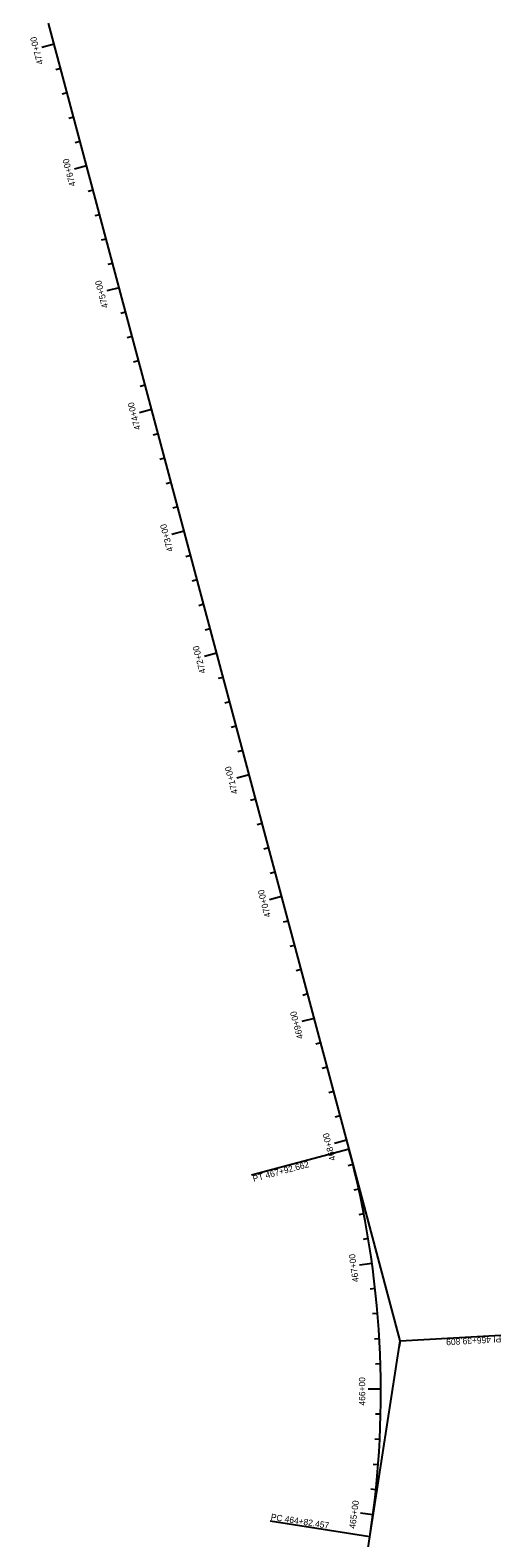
# Model space of a CAD drawing. Extents: x 187748 to 191086, y 249974 to 259749.
# Drawn here: x 189339 to 189712, y 253177 to 254373 of the extents above; entities that cross this region are included whole.
import ezdxf

# ---------------------------------------------------------------- set-up
doc = ezdxf.new("R2010")
doc.units = 0
doc.layers.add('BORDER', color=7, linetype='Continuous')

msp = doc.modelspace()

# ---------------------------------------------------------------- linework, layer by layer
at = {"layer": 'BORDER'}
for p, q in [((189591.5, 253485.3), (189353.2, 254378.6)), ((189357.6, 254362), (189347.9, 254359.4)), ((189362.8, 254342.7), (189358.9, 254341.7)), ((189367.9, 254323.4), (189364, 254322.3)), ((189373.1, 254304), (189369.2, 254303)), ((189378.2, 254284.7), (189374.4, 254283.7)), ((189383.4, 254265.4), (189373.7, 254262.8)), ((189388.5, 254246.1), (189384.7, 254245)), ((189393.7, 254226.7), (189389.8, 254225.7)), ((189398.8, 254207.4), (189395, 254206.4)), ((189404, 254188.1), (189400.1, 254187.1)), ((189409.1, 254168.8), (189399.5, 254166.2)), ((189414.3, 254149.5), (189410.4, 254148.4)), ((189419.5, 254130.1), (189415.6, 254129.1)), ((189424.6, 254110.8), (189420.7, 254109.8)), ((189429.8, 254091.5), (189425.9, 254090.4)), ((189434.9, 254072.2), (189425.3, 254069.6)), ((189440.1, 254052.8), (189436.2, 254051.8)), ((189445.2, 254033.5), (189441.4, 254032.5)), ((189450.4, 254014.2), (189446.5, 254013.2)), ((189455.5, 253994.9), (189451.7, 253993.8)), ((189460.7, 253975.5), (189451, 253973)), ((189465.9, 253956.2), (189462, 253955.2)), ((189471, 253936.9), (189467.1, 253935.9)), ((189476.2, 253917.6), (189472.3, 253916.5)), ((189481.3, 253898.2), (189477.5, 253897.2)), ((189486.5, 253878.9), (189476.8, 253876.3)), ((189491.6, 253859.6), (189487.8, 253858.6)), ((189496.8, 253840.3), (189492.9, 253839.2)), ((189501.9, 253820.9), (189498.1, 253819.9)), ((189507.1, 253801.6), (189503.2, 253800.6)), ((189512.3, 253782.3), (189502.6, 253779.7)), ((189517.4, 253763), (189513.5, 253761.9)), ((189522.6, 253743.6), (189518.7, 253742.6)), ((189527.7, 253724.3), (189523.9, 253723.3)), ((189532.9, 253705), (189529, 253704)), ((189538, 253685.7), (189528.4, 253683.1)), ((189543.2, 253666.3), (189539.3, 253665.3)), ((189548.3, 253647), (189544.5, 253646)), ((189553.5, 253627.7), (189549.6, 253626.7)), ((189558.6, 253608.4), (189554.8, 253607.3)), ((189563.8, 253589), (189554.1, 253586.5)), ((189569, 253569.7), (189565.1, 253568.7)), ((189574.1, 253550.4), (189570.3, 253549.4)), ((189579.3, 253531.1), (189575.4, 253530)), ((189584.4, 253511.8), (189580.6, 253510.7)), ((189589.6, 253492.4), (189579.9, 253489.9)), ((189591.5, 253485.3), (189514.2, 253464.7)), ((189594.6, 253473.1), (189590.8, 253472.1)), ((189599.2, 253453.6), (189595.3, 253452.7)), ((189603.2, 253434), (189599.3, 253433.3)), ((189606.8, 253414.3), (189602.8, 253413.7)), ((189609.8, 253394.6), (189599.9, 253393.2)), ((189612.2, 253374.7), (189608.3, 253374.3)), ((189614.2, 253354.8), (189610.2, 253354.5)), ((189615.6, 253334.9), (189611.6, 253334.6)), ((189632, 253333.3), (189630.7, 253338.1)), ((189632, 253333.3), (189711.9, 253337.6)), ((189632, 253333.3), (189631.3, 253328.4)), ((189616.5, 253314.9), (189612.5, 253314.8)), ((189616.8, 253294.9), (189606.8, 253294.8)), ((189616.6, 253274.9), (189612.6, 253275)), ((189615.9, 253254.9), (189611.9, 253255.1)), ((189614.6, 253234.9), (189610.7, 253235.2)), ((189612.9, 253215), (189608.9, 253215.4)), ((189608.1, 253177.8), (189529, 253190)), ((189610.5, 253195.2), (189600.6, 253196.4)), ((189531.2, 252679.3), (189608.1, 253177.8))]:
    msp.add_line(p, q, dxfattribs=at)
msp.add_lwpolyline([(189608.1, 253177.8), (189632, 253333.3), (189591.5, 253485.3)], dxfattribs=at)
msp.add_arc((188866.8, 253292), 750, 351.2393, 14.9372, dxfattribs=at)

# ---------------------------------------------------------------- texts
for s, rotation, p in [('477+00', 104.9372, (189349.1, 254346.6)), ('476+00', 104.9372, (189374.8, 254249.9)), ('475+00', 104.9372, (189400.6, 254153.3)), ('474+00', 104.9372, (189426.4, 254056.6)), ('473+00', 104.9372, (189452.2, 253960)), ('472+00', 104.9372, (189478, 253863.4)), ('471+00', 104.9372, (189503.5, 253767.7)), ('470+00', 104.9372, (189529.6, 253669.9)), ('469+00', 104.9372, (189555.3, 253573.4)), ('468+00', 104.9372, (189581.1, 253476.8)), ('PT 467+92.662', 14.9372, (189515.9, 253459.3)), ('467+00', 97.8583, (189599.3, 253380.1)), ('PI 466+39.809', 183.0882, (189712.1, 253337)), ('466+00', 90.2189, (189604.4, 253281.9)), ('465+00', 82.5795, (189596.5, 253183.9)), ('PC 464+82.457', 351.2393, (189529.2, 253191.2))]:
    msp.add_text(s, height=5, rotation=rotation, dxfattribs=at).set_placement(p)

doc.saveas('drawing.dxf')
